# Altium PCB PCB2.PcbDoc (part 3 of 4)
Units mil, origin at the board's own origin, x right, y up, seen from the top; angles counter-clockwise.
Board outline 7170.03 x 5785.03 mil, 4 copper layers (Top Layer, GND, PWR, Bottom Layer), stack 22.378 mil thick; 348 components, 320 nets, 1937 pads, 429 vias.
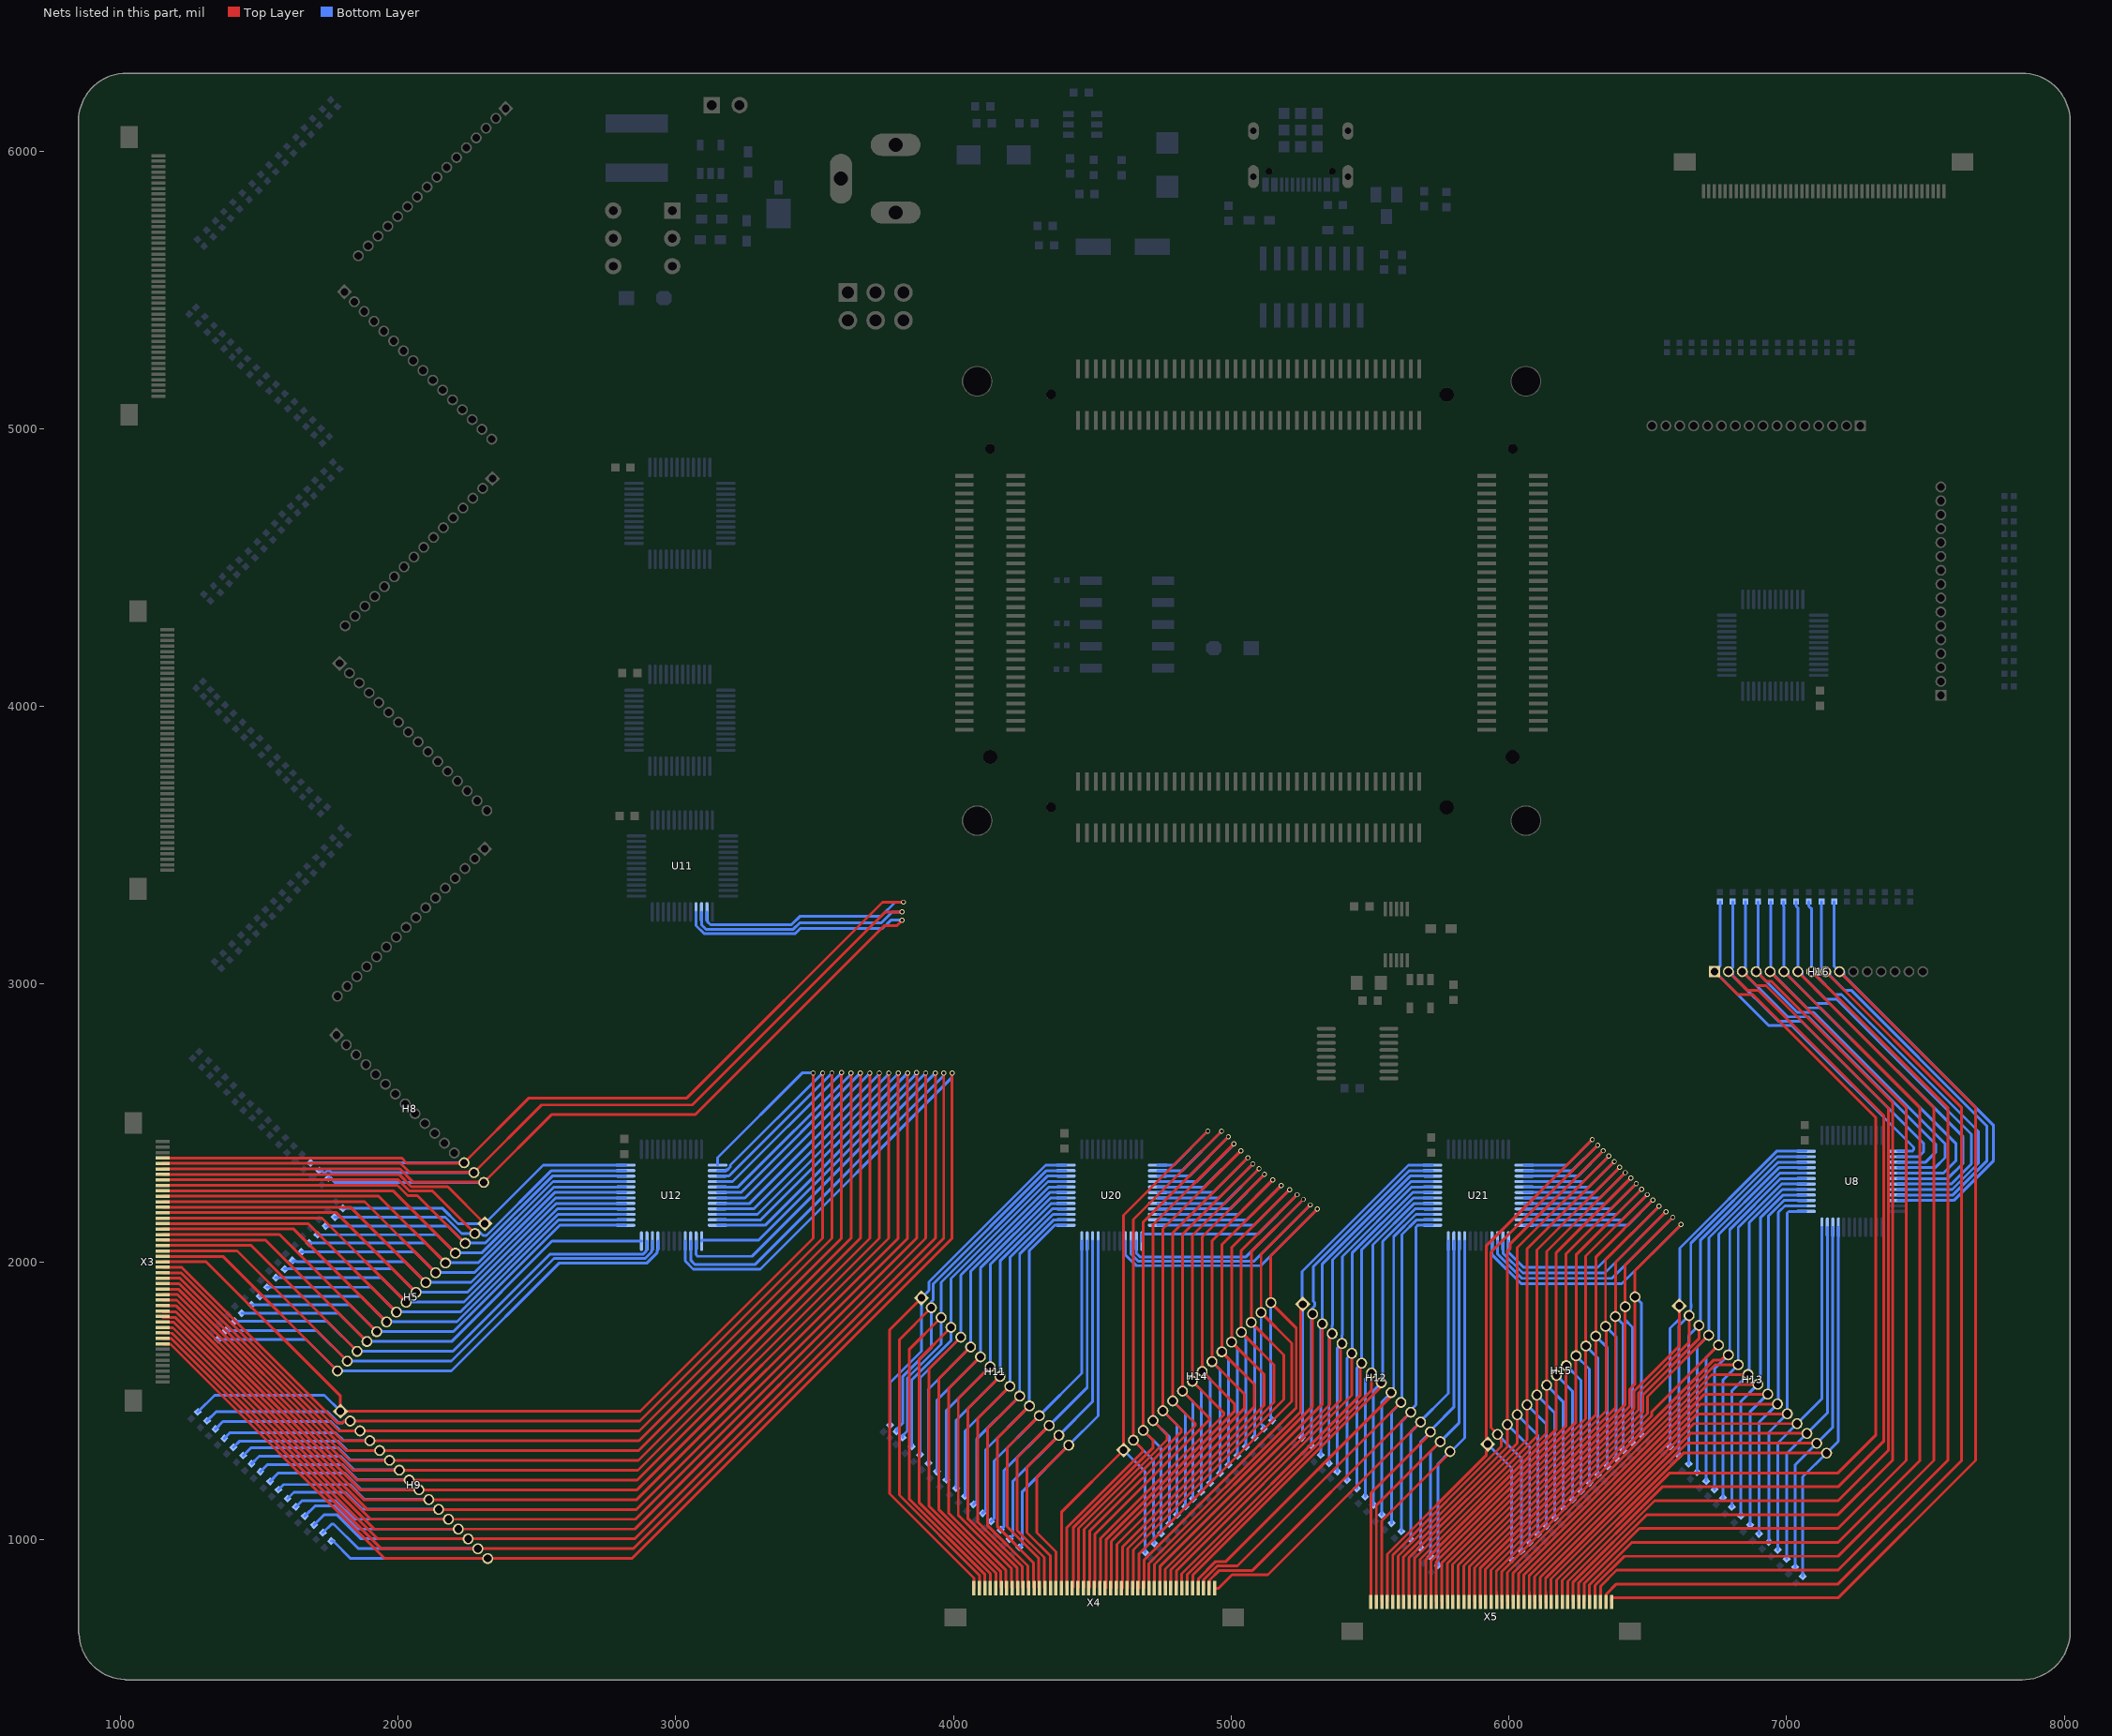
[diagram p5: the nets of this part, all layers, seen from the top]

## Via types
v1: diameter 18, hole 12, Top Layer to Bottom Layer, 429 vias

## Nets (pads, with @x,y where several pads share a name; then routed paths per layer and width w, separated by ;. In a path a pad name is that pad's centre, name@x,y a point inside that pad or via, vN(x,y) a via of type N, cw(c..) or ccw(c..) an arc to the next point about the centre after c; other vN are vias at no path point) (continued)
G93: H8.14 R201.2 U11.38 X3.4 | length 4400
  Top Layer w10: X3.4@1152.76,2374.02 2013,2374.02 2032.02,2355 2238.2,2355 H8.14@2240,2356.8 ; H8.14@2238.2,2356.8 2471.4,2590 3040,2590 3745,3295 v1(3820,3295)
  Bottom Layer w10: R201.2@1684.69,2356.89 1691.76,2356.89 1691.85,2356.8 H8.14@2238.2,2356.8 ; U11.38@3112.48,3260 3112.48,3229.8 3115.66,3226.62 3115.66,3223.24 3125.33,3213.57 3416.95,3213.57 3448.38,3245 3740,3245 3790,3295 v1(3820,3295)
G94: H8.15 R203.2 U11.39 X3.5 | length 4431.3
  Top Layer w10: X3.5@1152.76,2354.33 2010.06,2354.33 2042.28,2322.12 2272.88,2322.12 H8.15@2273.55,2321.45 2517.11,2565 3060,2565 3755,3260 v1(3815,3260)
  Bottom Layer w10: R203.2@1716.74,2328.94 1723.81,2328.94 1731.3,2321.45 1738.66,2321.45 1745.49,2328.28 1754.61,2328.28 1761.44,2321.45 H8.15@2273.55,2321.45 ; U11.39@3092.8,3260 3092.8,3213.68 3108.92,3197.57 3423.58,3197.57 3446.01,3220 3740,3220 3780,3260 v1(3815,3260)
G95: H8.16 R205.2 U11.40 X3.6 | length 4462.4
  Top Layer w10: X3.6@1152.76,2334.65 2007.12,2334.65 2055.01,2286.76 2308.24,2286.76 H8.16@2308.91,2286.09 2552.82,2530 3070,2530 3750,3210 3795,3210 v1(3815,3230)
  Bottom Layer w10: R205.2@1749.69,2301.89 1756.76,2301.89 1772.56,2286.09 H8.16@2308.91,2286.09 ; U11.40@3073.11,3260 3073.11,3210.74 3102.29,3181.57 3430.2,3181.57 3448.64,3200 3744.59,3200 3774.59,3230 v1(3815,3230)
G96: H5.1 R207.2 U12.12 X3.7 | length 2361.7
  Top Layer w10: X3.7@1152.76,2314.96 2004.18,2314.96 2048.38,2270.76 2179.21,2270.76 H5.1@2312.49,2137.49
  Bottom Layer w10: R207.2@1801.21,2192.36 2161.45,2192.36 2216.32,2137.49 H5.1@2312.49,2137.49 2523.27,2348.27 U12.12@2819.64,2348.27
G97: H5.2 R209.2 U12.11 X3.8 | length 2385
  Top Layer w10: X3.8@1152.76,2295.28 2001.23,2295.28 2041.75,2254.76 2124.5,2254.76 H5.2@2277.13,2102.13
  Bottom Layer w10: R209.2@1772.21,2160.6 2170.58,2160.6 2229.05,2102.13 H5.2@2277.13,2102.13 2287.96,2112.96 2306.27,2094.65 2318.7,2094.65 2552.63,2328.58 U12.11@2819.64,2328.58
G98: H5.3 R211.2 U12.10 X3.9 | length 2390.2
  Top Layer w10: X3.9@1152.76,2275.59 1998.3,2275.59 2035.12,2238.76 2069.79,2238.76 H5.3@2241.78,2066.78
  Bottom Layer w10: R211.2@1739.26,2128.55 2180.01,2128.55 H5.3@2241.78,2066.78 2252.61,2077.61 2262.77,2067.45 2314.13,2067.45 2555.58,2308.9 U12.10@2819.64,2308.9
G99: H5.4 R213.2 U12.9 X3.10 | length 2398.8
  Top Layer w10: X3.10@1152.76,2255.91 1981.93,2255.91 H5.4@2206.42,2031.42
  Bottom Layer w10: R213.2@1710.16,2097.64 2140.2,2097.64 H5.4@2206.42,2031.42 2217.25,2042.25 2227.41,2032.09 2301.4,2032.09 2558.52,2289.21 U12.9@2819.64,2289.21
G100: H5.5 R215.2 U12.8 X3.11 | length 2408.6
  Top Layer w10: X3.11@1152.76,2236.22 1930.91,2236.22 H5.5@2171.07,1996.07
  Bottom Layer w10: R215.2@1680.16,2067.64 2099.49,2067.64 H5.5@2171.07,1996.07 2181.9,2006.9 2192.05,1996.74 2288.67,1996.74 2561.46,2269.53 U12.8@2819.64,2269.53
G101: H5.6 R217.2 U12.7 X3.12 | length 2415.6
  Top Layer w10: X3.12@1152.76,2216.54 1879.88,2216.54 H5.6@2135.71,1960.71
  Bottom Layer w10: R217.2@1652.21,2035.6 1652.57,2035.24 2061.18,2035.24 H5.6@2135.71,1960.71 2146.54,1971.54 2156.7,1961.38 2275.94,1961.38 2564.4,2249.84 U12.7@2819.64,2249.84
G102: H5.7 R219.2 U12.6 X3.13 | length 2429.3
  Top Layer w10: X3.13@1152.76,2196.85 1828.86,2196.85 H5.7@2100.36,1925.36
  Bottom Layer w10: R219.2@1619.82,2000 1624.46,2004.64 1628.32,2004.64 1632.96,2000 2025.71,2000 H5.7@2100.36,1925.36 2111.18,1936.18 2121.34,1926.03 2263.21,1926.03 2567.35,2230.16 U12.6@2819.64,2230.16
G103: H5.8 R221.2 U12.5 X3.14 | length 2435.2
  Top Layer w10: X3.14@1152.76,2177.17 1777.83,2177.17 H5.8@2065,1890
  Bottom Layer w10: R221.2@1592.21,1975.6 1979.4,1975.6 H5.8@2065,1890 2075.83,1900.83 2085.99,1890.67 2250.49,1890.67 2570.29,2210.47 U12.5@2819.64,2210.47
G104: H5.9 R223.2 U12.4 X3.15 | length 2445.9
  Top Layer w10: X3.15@1152.76,2157.48 1726.81,2157.48 H5.9@2029.64,1854.64
  Bottom Layer w10: R223.2@1560.16,1942.64 1941.64,1942.64 H5.9@2029.64,1854.64 2040.47,1865.47 2050.63,1855.32 2237.76,1855.32 2573.23,2190.79 U12.4@2819.64,2190.79
G105: H5.10 R225.2 U12.3 X3.16 | length 2455
  Top Layer w10: X3.16@1152.76,2137.8 1675.78,2137.8 H5.10@1994.29,1819.29
  Bottom Layer w10: R225.2@1529.26,1908.55 1905.03,1908.55 H5.10@1994.29,1819.29 2005.12,1830.12 2015.28,1819.96 2225.03,1819.96 2576.17,2171.1 U12.3@2819.64,2171.1
G106: H5.11 R227.2 U12.2 X3.17 | length 2460.6
  Top Layer w10: X3.17@1152.76,2118.11 1624.76,2118.11 H5.11@1958.93,1783.93
  Bottom Layer w10: R227.2@1502.21,1875.6 1867.27,1875.6 H5.11@1958.93,1783.93 1969.76,1794.76 1979.92,1784.6 2212.3,1784.6 2579.12,2151.42 U12.2@2819.64,2151.42
G107: H5.12 R229.2 U12.1 X3.18 | length 2470.5
  Top Layer w10: X3.18@1152.76,2098.43 1573.73,2098.43 H5.12@1923.58,1748.58
  Bottom Layer w10: R229.2@1472.21,1845.6 1826.56,1845.6 H5.12@1923.58,1748.58 1934.41,1759.41 1944.57,1749.25 2199.57,1749.25 2582.06,2131.73 U12.1@2819.64,2131.73
G108: H5.13 R231.2 U12.48 X3.19 | length 2518.5
  Top Layer w10: X3.19@1152.76,2078.74 1522.71,2078.74 H5.13@1888.22,1713.22
  Bottom Layer w10: R231.2@1437.21,1815.6 1785.85,1815.6 H5.13@1888.22,1713.22 2193.22,1713.22 2554.64,2074.64 U12.48@2876.73,2074.64
G109: H5.14 R233.2 U12.47 X3.20 | length 2570.9
  Top Layer w10: X3.20@1152.76,2059.06 1471.67,2059.06 H5.14@1852.87,1677.87
  Bottom Layer w10: R233.2@1412.21,1785.6 1745.14,1785.6 H5.14@1852.87,1677.87 2197.87,1677.87 2548.21,2028.21 2883.57,2028.21 2893.24,2037.88 2893.24,2041.27 2896.42,2044.45 U12.47@2896.42,2074.64
G110: H5.15 R235.2 U12.46 X3.21 | length 2611.1
  Top Layer w10: X3.21@1152.76,2039.37 1420.66,2039.37 H5.15@1817.51,1642.51
  Bottom Layer w10: R235.2@1380.16,1752.64 1707.38,1752.64 H5.15@1817.51,1642.51 2192.51,1642.51 2562.21,2012.21 2890.2,2012.21 2912.93,2034.95 2912.93,2040.83 2912.93,2041.28 2916.1,2044.45 U12.46@2916.1,2074.64
G111: H5.16 R237.2 U12.45 X3.22 | length 2647.6
  Top Layer w10: X3.22@1152.76,2019.69 1369.62,2019.69 H5.16@1782.16,1607.16
  Bottom Layer w10: R237.2@1352.21,1720.6 1668.72,1720.6 H5.16@1782.16,1607.16 2192.16,1607.16 2581.21,1996.21 2896.82,1996.21 2932.61,2032 2932.61,2040.82 2932.61,2041.27 2935.79,2044.45 U12.45@2935.79,2074.64
G112: H9.1 R239.2 U12.25 X3.23 | length 4510.3
  Top Layer w10: X3.23@1152.76,2000 1310,2000 1792.87,1517.13 H9.1@1792.87,1462.13 2872.13,1462.13 3495,2085 v1(3495,2680)
  Bottom Layer w10: R239.2@1279.66,1459.69 1339.97,1520 1735,1520 H9.1@1792.87,1462.13 ; U12.25@3150.36,2348.27 3150.36,2375.36 3455,2680 v1(3495,2680)
G113: H9.2 R241.2 U12.26 X3.24 | length 4556.3
  Top Layer w10: X3.24@1152.76,1980.32 1221.31,1980.32 1782.34,1419.29 1799.08,1419.29 1806.56,1426.78 H9.2@1828.22,1426.78 2870.78,1426.78 3529,2085 v1(3529,2680)
  Bottom Layer w10: R241.2@1312.61,1427.64 1344.97,1460 1745.95,1460 1786.65,1419.29 1799.08,1419.29 1806.56,1426.78 H9.2@1828.22,1426.78 ; U12.26@3150.36,2328.58 3180.55,2328.58 3183.73,2331.76 3187.12,2331.76 3196.79,2341.43 3196.79,2347.79 v1(3529,2680)
G114: H9.3 R243.2 U12.27 X3.25 | length 4641.1
  Top Layer w10: X3.25@1152.76,1960.63 1218.37,1960.63 1787.58,1391.42 H9.3@1863.58,1391.42 2868.96,1391.42 3562.54,2085 v1(3562.54,2680.46)
  Bottom Layer w10: R243.2@1342.61,1397.64 1369.97,1425 1758.32,1425 1791.23,1392.09 1862.91,1392.09 H9.3@1863.58,1391.42 ; U12.27@3150.36,2308.9 3150.55,2309.1 3192.04,2309.1 3562.54,2679.6 v1(3562.54,2680.46)
G115: H9.4 R245.2 U12.28 X3.26 | length 4738
  Top Layer w10: X3.26@1152.76,1940.95 1215.43,1940.95 1800.31,1356.07 H9.4@1898.93,1356.07 2868.07,1356.07 3597,2085 v1(3597,2680.99)
  Bottom Layer w10: R245.2@1374.66,1364.69 1394.97,1385 1775.69,1385 1803.96,1356.74 1898.26,1356.74 H9.4@1898.93,1356.07 ; U12.28@3150.36,2289.21 3205.22,2289.21 v1(3597,2680.99)
G116: H9.5 R247.2 U12.29 X3.27 | length 4843.4
  Top Layer w10: X3.27@1152.76,1921.26 1212.49,1921.26 1813.04,1320.71 H9.5@1934.29,1320.71 2866.71,1320.71 3631,2085 v1(3631,2680)
  Bottom Layer w10: R247.2@1407.61,1332.64 1429.97,1355 1783.07,1355 1816.68,1321.38 1933.62,1321.38 H9.5@1934.29,1320.71 ; U12.29@3150.36,2269.53 3224.53,2269.53 v1@3635,2680
G117: H9.6 R249.2 U12.30 X3.28 | length 4943.4
  Top Layer w10: X3.28@1152.76,1901.58 1209.54,1901.58 1825.77,1285.36 H9.6@1969.64,1285.36 2865.36,1285.36 3665,2085 v1(3665,2680)
  Bottom Layer w10: R249.2@1442.61,1302.64 1469.97,1330 1785.44,1330 1829.41,1286.03 1968.97,1286.03 H9.6@1969.64,1285.36 ; U12.30@3150.36,2249.84 3234.84,2249.84 v1(3665,2680)
G118: H9.7 R251.2 U12.31 X3.29 | length 5048.3
  Top Layer w10: X3.29@1152.76,1881.89 1206.6,1881.89 1838.5,1250 H9.7@2005,1250 2864,1250 3699,2085 v1(3699,2680)
  Bottom Layer w10: R251.2@1472.61,1272.64 1499.97,1300 1792.81,1300 1842.14,1250.67 2004.33,1250.67 H9.7@2005,1250 ; U12.31@3150.36,2230.16 3249.16,2230.16 v1(3699,2680)
G119: H9.8 R253.2 U12.32 X3.30 | length 5151.1
  Top Layer w10: X3.30@1152.76,1862.21 1203.66,1862.21 1851.22,1214.64 H9.8@2040.36,1214.64 2862.64,1214.64 3733,2085 v1(3733,2680)
  Bottom Layer w10: R253.2@1504.66,1244.69 1529.97,1270 1800.18,1270 1854.87,1215.32 2039.68,1215.32 H9.8@2040.36,1214.64 ; U12.32@3150.36,2210.47 3266.53,2210.47 v1@3734.53,2678.47
G120: H9.9 R255.2 U12.33 X3.31 | length 5254.6
  Top Layer w10: X3.31@1152.76,1842.52 1200.72,1842.52 1863.95,1179.29 H9.9@2075.71,1179.29 2861.29,1179.29 3767,2085 v1(3767,2680)
  Bottom Layer w10: R255.2@1540.02,1210.05 1569.97,1240 1807.56,1240 1867.6,1179.96 2075.04,1179.96 H9.9@2075.71,1179.29 ; U12.33@3150.36,2190.79 3280.79,2190.79 v1@3770,2680
G121: H9.10 R257.2 U12.34 X3.32 | length 5350.8
  Top Layer w10: X3.32@1152.76,1822.84 1152.76,1820.06 1200.56,1820.06 1876.68,1143.93 H9.10@2111.07,1143.93 2859.93,1143.93 3801,2085 v1(3801,2680)
  Bottom Layer w10: R257.2@1569.66,1179.69 1588.14,1198.17 1826.75,1198.17 1880.32,1144.6 2110.4,1144.6 H9.10@2111.07,1143.93 ; U12.34@3150.36,2171.1 3294.32,2171.1 3797,2673.78 3797,2673.84 3802.97,2679.81 v1@3803.03,2679.81
G122: H9.11 R259.2 U12.35 X3.33 | length 5452.6
  Top Layer w10: X3.33@1152.76,1803.15 1152.76,1800.38 1197.61,1800.38 1889.41,1108.58 H9.11@2146.42,1108.58 2858.58,1108.58 3835,2085 v1(3835,2680)
  Bottom Layer w10: R259.2@1602.97,1148 1624.97,1170 1809.67,1170 1870.42,1109.25 2145.75,1109.25 H9.11@2146.42,1108.58 ; U12.35@3150.36,2151.42 3306.42,2151.42 v1(3835,2680)
G123: H9.12 R261.2 U12.36 X3.34 | length 5557.3
  Top Layer w10: X3.34@1152.76,1783.47 1153.66,1782.57 1192.79,1782.57 1902.14,1073.22 H9.12@2181.78,1073.22 2855.75,1073.22 3867.53,2085 v1(3867.53,2681.47)
  Bottom Layer w10: R261.2@1632.61,1117.64 1654.34,1139.37 1775.63,1139.37 1841.78,1073.22 H9.12@2181.78,1073.22 ; U12.36@3150.36,2131.73 3321.73,2131.73 3859,2669 3859,2670.78 3867.53,2679.31 v1(3867.53,2681.47)
G124: H9.13 R263.2 U12.37 X3.35 | length 5737.4
  Top Layer w10: X3.35@1152.76,1763.78 1153.66,1762.88 1189.86,1762.88 1914.86,1037.87 H9.13@2217.13,1037.87 2852.87,1037.87 3900,2085 v1(3900,2680)
  Bottom Layer w10: R263.2@1664.66,1084.69 1700.84,1120.87 1771.5,1120.87 1854.5,1037.87 H9.13@2217.13,1037.87 ; U12.37@3093.27,2074.64 3093.27,2077.03 3093.74,2077.5 3297.5,2077.5 v1(3900,2680)
G125: H9.14 R265.2 U12.38 X3.36 | length 5925.4
  Top Layer w10: X3.36@1152.76,1744.1 1153.66,1743.2 1186.91,1743.2 1927.59,1002.51 H9.14@2252.49,1002.51 2852.51,1002.51 3935,2085 v1(3935,2680)
  Bottom Layer w10: R265.2@1697.61,1052.64 1734.97,1090 1779.75,1090 1867.23,1002.51 H9.14@2252.49,1002.51 ; U12.38@3073.58,2074.64 3073.58,2025.86 3079.44,2020 3275,2020 v1(3935,2680)
G126: H9.15 R267.2 U12.39 X3.37 | length 6069.3
  Top Layer w10: X3.37@1152.76,1724.41 1153.66,1723.51 1183.97,1723.51 1940.32,967.16 H9.15@2287.84,967.16 2847.16,967.16 3965,2085 v1(3965,2680)
  Bottom Layer w10: R267.2@1730.02,1025.05 1760.84,1055.87 1769.13,1055.87 1857.84,967.16 H9.15@2287.84,967.16 ; U12.39@3053.9,2074.64 3053.9,2006.1 3070,1990 3285,1990 3963.47,2668.47 3963.47,2678.47 v1(3965,2680)
G127: H9.16 R269.2 U12.40 X3.38 | length 6170.2
  Top Layer w10: X3.38@1152.76,1704.73 1153.66,1703.83 1181.02,1703.83 1953.05,931.8 H9.16@2323.2,931.8 2841.8,931.8 3995,2085 v1(3995,2680)
  Bottom Layer w10: R269.2@1759.66,994.69 1766.73,994.69 1829.62,931.8 H9.16@2323.2,931.8 ; U12.40@3034.21,2074.64 3034.21,2003.16 3063.37,1974 3304,1974 3995,2665 v1(3995,2680)
G128: H11.1 R13.2 U20.12 X4.1 | length 2459.6
  Top Layer w10: H11.1@3884.84,1870.16 3769.84,1755.16 3769.84,1165.17 4073.82,861.18 X4.1@4073.82,825
  Bottom Layer w10: R13.2@3772.05,1412.05 3772.05,1565.05 3884.84,1677.83 H11.1@3884.84,1870.16 3911.67,1897 3911.67,1928.09 4331.85,2348.27 U20.12@4404.64,2348.27
G129: H11.2 R15.2 U20.11 X4.2 | length 2408.9
  Top Layer w10: H11.2@3920.19,1834.81 3805.19,1719.81 3805.19,1159.81 4093.5,871.5 X4.2@4093.5,824.94
  Bottom Layer w10: R15.2@3795,1390 3795,1397.07 3818,1420.07 3818,1588.37 3920.19,1690.56 H11.2@3920.19,1834.81 3920.19,1856.47 3927.67,1863.95 3927.67,1921.47 4334.79,2328.58 U20.11@4404.64,2328.58
G130: H11.3 R17.2 U20.10 X4.3 | length 2359.5
  Top Layer w10: H11.3@3955.55,1799.45 3840.55,1684.45 3840.55,1147.08 4113.19,874.44 X4.3@4113.19,825
  Bottom Layer w10: R17.2@3817.05,1367.05 3817.05,1374.12 3834,1391.07 3834,1581.74 3955.55,1703.29 H11.3@3955.55,1799.45 3955.55,1926.71 4337.73,2308.9 U20.10@4404.64,2308.9
G131: H11.4 R19.2 U20.9 X4.4 | length 2314.6
  Top Layer w10: H11.4@3990.9,1764.1 3875.9,1649.1 3875.9,1134.35 4132.87,877.38 X4.4@4132.87,825
  Bottom Layer w10: R19.2@3850,1335 3850,1575.11 3990.9,1716.02 H11.4@3990.9,1764.1 3990.9,1939.44 4340.67,2289.21 U20.9@4404.64,2289.21
G132: H11.5 R21.2 U20.8 X4.5 | length 2268.9
  Top Layer w10: H11.5@4026.26,1728.74 3911.26,1613.74 3911.26,1121.63 4152.56,880.32 X4.5@4152.56,825
  Bottom Layer w10: R21.2@3880,1305 3880,1582.49 H11.5@4026.26,1728.74 4026.26,1952.17 4343.62,2269.53 U20.8@4404.64,2269.53
G133: H11.6 R23.2 U20.7 X4.6 | length 2223.2
  Top Layer w10: H11.6@4061.61,1693.39 3946.61,1578.39 3946.61,1108.9 4169.47,886.04 4169.47,827.77 X4.6@4172.24,825
  Bottom Layer w10: R23.2@3910,1275 3910,1541.78 H11.6@4061.61,1693.39 4061.61,1964.9 4346.56,2249.84 U20.7@4404.64,2249.84
G134: H11.7 R25.2 U20.6 X4.7 | length 2177.6
  Top Layer w10: H11.7@4096.97,1658.03 3981.97,1543.03 3981.97,1096.17 4189.15,888.99 4189.15,827.78 X4.7@4191.93,825
  Bottom Layer w10: R25.2@3940,1245 3940,1501.07 H11.7@4096.97,1658.03 4096.97,1977.62 4349.5,2230.16 U20.6@4404.64,2230.16
G135: H11.8 R27.2 U20.5 X4.8 | length 2129.8
  Top Layer w10: H11.8@4132.32,1622.68 4017.32,1507.68 4017.32,1087.68 4208.84,896.16 4208.84,827.77 X4.8@4211.61,825
  Bottom Layer w10: R27.2@3975,1215 3975,1465.36 H11.8@4132.32,1622.68 4132.32,1990.35 4352.44,2210.47 U20.5@4404.64,2210.47
G136: H11.9 R29.2 U20.4 X4.9 | length 2082.1
  Top Layer w10: H11.9@4167.68,1587.32 4052.68,1472.32 4052.68,1074.95 4228.52,899.11 4228.52,827.78 X4.9@4231.3,825
  Bottom Layer w10: R29.2@4010,1185 4010,1429.64 H11.9@4167.68,1587.32 4167.68,2003.08 4355.39,2190.79 U20.4@4404.64,2190.79
G137: H11.10 R31.2 U20.3 X4.10 | length 2033.5
  Top Layer w10: H11.10@4203.03,1551.97 4088.03,1436.97 4088.03,1062.22 4248.21,902.05 4248.21,827.77 X4.10@4250.98,825
  Bottom Layer w10: R31.2@4042.05,1157.05 4042.05,1390.98 H11.10@4203.03,1551.97 4203.03,2015.81 4358.33,2171.1 U20.3@4404.64,2171.1
G138: H11.11 R33.2 U20.2 X4.11 | length 1987.8
  Top Layer w10: H11.11@4238.39,1516.61 4123.39,1401.61 4123.39,1049.49 4267.89,905 4267.89,827.78 X4.11@4270.67,825
  Bottom Layer w10: R33.2@4072.05,1127.05 4083.46,1138.46 4083.46,1361.68 H11.11@4238.39,1516.61 4238.39,2028.53 4361.27,2151.42 U20.2@4404.64,2151.42
G139: H11.12 R35.2 U20.1 X4.12 | length 1942.9
  Top Layer w10: H11.12@4273.74,1481.26 4158.74,1366.26 4158.74,1046.26 4287.58,917.42 4287.58,827.77 X4.12@4290.35,825
  Bottom Layer w10: R35.2@4105,1095 4116.41,1106.41 4116.41,1323.92 H11.12@4273.74,1481.26 4273.74,2041.26 4364.21,2131.73 U20.1@4404.64,2131.73
G140: H11.13 R37.2 U20.48 X4.13 | length 1861.5
  Top Layer w10: H11.13@4309.1,1445.9 4194.1,1330.9 4194.1,1045.9 4307.26,932.74 4307.26,827.78 X4.13@4310.04,825
  Bottom Layer w10: R37.2@4135,1065 4146.41,1076.41 4146.41,1283.21 H11.13@4309.1,1445.9 4461.73,1598.53 U20.48@4461.73,2074.64
G141: H11.14 R39.2 U20.47 X4.14 | length 1843.3
  Top Layer w10: X4.14@4329.72,825 4326.95,827.77 4326.95,935.68 4229.45,1033.17 4229.45,1295.55 H11.14@4344.45,1410.55
  Bottom Layer w10: R39.2@4170,1035 4181.41,1046.41 4181.41,1247.5 H11.14@4344.45,1410.55 4481.42,1547.51 U20.47@4481.42,2074.64
G142: H11.15 R41.2 U20.46 X4.15 | length 1829.3
  Top Layer w10: X4.15@4349.41,825 4349.41,940.59 4264.81,1025.19 4264.81,1260.19 H11.15@4379.81,1375.19
  Bottom Layer w10: R41.2@4202.05,1002.05 4213.46,1013.46 4213.46,1208.84 H11.15@4379.81,1375.19 4501.1,1496.48 U20.46@4501.1,2074.64
G143: H11.16 R43.2 U20.45 X4.16 | length 1811.1
  Top Layer w10: X4.16@4369.09,825 4369.09,955.91 4300.16,1024.84 4300.16,1224.84 H11.16@4415.16,1339.84
  Bottom Layer w10: R43.2@4237.05,972.05 4248.46,983.46 4248.46,1173.13 H11.16@4415.16,1339.84 4520.79,1445.46 U20.45@4520.79,2074.64
G144: H14.1 R45.2 U20.25 X4.17 | length 2496.4
  Top Layer w10: X4.17@4388.78,825 4388.78,1098.78 H14.1@4612.51,1322.51 4612.51,2167.51 v1(4916,2471)
  Bottom Layer w10: H14.1@4612.51,1322.51 4689.91,1245.12 R45.2@4689.91,954.01 ; U20.25@4735.36,2348.27 4793.27,2348.27 v1(4916,2471)
G145: H14.2 R47.2 U20.26 X4.18 | length 2593
  Top Layer w10: X4.18@4408.46,825 4408.46,1043.46 4681.23,1316.23 4681.23,1324.51 H14.2@4647.87,1357.87 4647.87,2152.87 v1(4965,2470)
  Bottom Layer w10: H14.2@4647.87,1357.87 4720.57,1285.17 4720.57,1017.76 4721.96,1016.37 R47.2@4721.96,986.96 ; U20.26@4735.36,2328.58 4823.58,2328.58 v1(4965,2470)
G146: H14.3 R49.2 U20.27 X4.19 | length 2598.2
  Top Layer w10: X4.19@4428.15,825 4430.92,827.77 4430.92,1043.3 4719.08,1331.45 4719.08,1357.37 H14.3@4683.22,1393.22 4683.22,2143.22 v1(4990,2450)
  Bottom Layer w10: H14.3@4683.22,1393.22 4746.96,1329.49 R49.2@4746.96,1021.96 ; U20.27@4735.36,2308.9 4848.9,2308.9 v1(4990,2450)
G147: H14.4 R51.2 U20.28 X4.20 | length 2603
  Top Layer w10: X4.20@4447.83,825 4450.61,827.78 4450.61,1040.36 4769.44,1359.18 4769.44,1377.72 H14.4@4718.58,1428.58 4718.58,2133.58 v1(5010,2425)
  Bottom Layer w10: H14.4@4718.58,1428.58 4776.96,1370.2 R51.2@4776.96,1056.96 ; U20.28@4735.36,2289.21 4876.37,2289.21 5010,2422.84 v1(5010,2425)
G148: H14.5 R53.2 U20.29 X4.21 | length 2614.3
  Top Layer w10: X4.21@4467.52,825 4470.29,827.77 4470.29,1037.41 4819.79,1386.91 4819.79,1398.08 H14.5@4753.93,1463.93 4753.93,2118.93 v1(5035,2400)
  Bottom Layer w10: U20.29@4735.36,2269.53 4903.47,2269.53 5033.94,2400 v1(5035,2400) ; H14.5@4753.93,1463.93 4804.91,1412.96 R53.2@4804.91,1089.01
G149: H14.6 R55.2 U20.30 X4.22 | length 2629.9
  Top Layer w10: X4.22@4487.2,825 4489.98,827.78 4489.98,1029.98 4870.15,1410.15 4870.15,1418.43 H14.6@4789.29,1499.29 4789.29,2104.29 v1(5060,2375)
  Bottom Layer w10: U20.30@4735.36,2249.84 4934.84,2249.84 v1(5060,2375) ; H14.6@4789.29,1499.29 4834.91,1453.67 R55.2@4834.91,1119.01
G150: H14.7 R57.2 U20.31 X4.23 | length 2639.2
  Top Layer w10: X4.23@4506.89,825 4509.66,827.77 4509.66,1019.66 4920.5,1430.5 4920.5,1438.79 H14.7@4824.64,1534.64 4824.64,2098.93 v1(5077.86,2352.14)
  Bottom Layer w10: U20.31@4735.36,2230.16 4955.88,2230.16 v1(5077.86,2352.14) ; H14.7@4824.64,1534.64 4861.96,1497.33 R57.2@4861.96,1146.96
G151: H14.8 R59.2 U20.32 X4.24 | length 2670.3
  Top Layer w10: X4.24@4526.57,825 4526.57,845.59 4528.98,845.59 4529.35,845.96 4529.35,1004.35 4973.36,1448.36 4973.36,1456.64 H14.8@4860,1570 4860,2095 v1(5100,2335)
  Bottom Layer w10: U20.32@4735.36,2210.47 4975.47,2210.47 v1(5100,2335) ; H14.8@4860,1570 4891.96,1538.04 R59.2@4891.96,1171.96
G152: H14.9 R61.2 U20.33 X4.25 | length 2676.3
  Top Layer w10: X4.25@4546.26,825 4549.03,825 4549.03,999.03 5012.86,1462.86 5012.86,1487.86 H14.9@4895.36,1605.36 4895.36,2090.36 v1(5120,2315)
  Bottom Layer w10: U20.33@4735.36,2190.79 4995.79,2190.79 v1(5120,2315) ; H14.9@4895.36,1605.36 4924.91,1575.8 R61.2@4924.91,1204.01
G153: H14.10 R63.2 U20.34 X4.26 | length 2690.7
  Top Layer w10: X4.26@4565.94,825 4568.72,825 4568.72,993.72 5048.21,1473.21 5048.21,1523.21 H14.10@4930.71,1640.71 4930.71,2075.71 v1(5150,2295)
  Bottom Layer w10: U20.34@4735.36,2171.1 5026.1,2171.1 v1(5150,2295) ; H14.10@4930.71,1640.71 4959.91,1611.51 R63.2@4959.91,1239.01
G154: H14.11 R65.2 U20.35 X4.27 | length 2707.9
  Top Layer w10: X4.27@4585.63,825 4588.4,825 4588.4,983.4 5083.57,1478.57 5083.57,1558.57 H14.11@4966.07,1676.07 4966.07,2061.07 v1(5180,2275)
  Bottom Layer w10: U20.35@4735.36,2151.42 5056.42,2151.42 v1(5180,2275) ; H14.11@4966.07,1676.07 4989.91,1652.22 R65.2@4989.91,1269.01
G155: H14.12 R67.2 U20.36 X4.28 | length 2730.2
  Top Layer w10: X4.28@4605.31,825 4608.09,825 4608.09,973.09 5118.92,1483.92 5118.92,1593.92 H14.12@5001.42,1711.42 5001.42,2051.42 v1(5210,2260)
  Bottom Layer w10: U20.36@4735.36,2131.73 5081.73,2131.73 v1(5210,2260) ; H14.12@5001.42,1711.42 5021.96,1690.88 R67.2@5021.96,1301.96
G156: H14.13 R69.2 U20.37 X4.29 | length 2833
  Top Layer w10: X4.29@4625,825 4627.77,825 4627.77,967.77 5154.28,1494.28 5154.28,1629.28 H14.13@5036.78,1746.78 5035,1748.55 5035,2039.2 v1(5237.6,2241.8)
  Bottom Layer w10: U20.37@4678.27,2074.64 4678.27,2099.09 4678.74,2099.57 5095.36,2099.57 v1(5237.6,2241.8) ; H14.13@5036.78,1746.78 5052.55,1731 R69.2@5052.55,1334.17
G157: H14.14 R71.2 U20.38 X4.30 | length 2909.9
  Top Layer w10: X4.30@4644.68,825 4647.46,825 4647.46,962.46 5189.63,1504.63 5189.63,1664.63 H14.14@5072.13,1782.13 5072.13,2037.13 v1(5260,2225)
  Bottom Layer w10: U20.38@4658.58,2074.64 4658.58,2031.27 4671.64,2018.21 5053.21,2018.21 v1(5260,2225) ; H14.14@5072.13,1782.13 5084.6,1769.66 R71.2@5084.6,1367.12
G158: H14.15 R73.2 U20.39 X4.31 | length 2940
  Top Layer w10: X4.31@4664.37,825 4667.14,825 4667.14,947.14 5218,1498 5218,1706.97 H14.15@5107.49,1817.49 5107.49,2027.49 v1(5285,2205)
  Bottom Layer w10: U20.39@4638.9,2074.64 4638.9,2028.33 4665.02,2002.21 5082.21,2002.21 v1(5285,2205) ; H14.15@5107.49,1817.49 5107.49,1416.31 5117.55,1406.24 R73.2@5117.55,1399.17
G159: H14.16 R75.2 U20.40 X4.32 | length 2967.7
  Top Layer w10: X4.32@4684.05,825 4686.83,825 4686.83,926.83 5234,1474 5234,1761.69 H14.16@5142.84,1852.84 5142.84,2022.84 v1(5310,2190)
  Bottom Layer w10: U20.40@4619.21,2074.64 4619.21,2025.39 4658.39,1986.21 5106.21,1986.21 v1(5310,2190) ; H14.16@5142.84,1852.84 5142.84,1440.95 5147.55,1436.24 R75.2@5147.55,1429.17
G160: H12.1 R77.2 U21.12 X4.33 | length 2476.8
  Top Layer w10: X4.33@4703.74,825 4703.74,913.74 5250,1460 5250,1834.92 5252.16,1837.07 5252.16,1848.31 H12.1@5250,1850.47
  Bottom Layer w10: R77.2@5254.28,1366.52 5254.28,1373.59 5257.51,1376.82 H12.1@5257.51,1847.49 ; H12.1@5255,1854.36 5255,1865.74 5257.51,1868.26 5255,1870.77 5255,1964.77 5638.5,2348.27 U21.12@5724.64,2348.27
G161: H12.2 R79.2 U21.11 X4.34 | length 2430.6
  Top Layer w10: X4.34@4723.42,825 4723.42,910.79 5292.87,1480.24 H12.2@5292.87,1812.13
  Bottom Layer w10: R79.2@5289.28,1336.52 5289.28,1808.54 H12.2@5292.87,1812.13 ; H12.2@5290.29,1831.21 5300.35,1841.27 5300.35,1853.7 5295,1859.06 5295,1982.14 5641.43,2328.58 U21.11@5724.64,2328.58
G162: H12.3 R81.2 U21.10 X4.35 | length 2412.3
  Top Layer w10: X4.35@4743.11,825 4743.11,903.11 5328.22,1488.22 H12.3@5328.22,1776.78
  Bottom Layer w10: R81.2@5322.23,1304.47 5322.23,1770.78 H12.3@5328.22,1776.78 5328.22,1992.74 5644.38,2308.9 U21.10@5724.64,2308.9
G163: H12.4 R83.2 U21.9 X4.36 | length 2377.7
  Top Layer w10: X4.36@4762.79,825 4762.79,893.68 5355,1485.89 H12.4@5355,1754.43
  Bottom Layer w10: R83.2@5352.23,1274.47 5352.23,1730.07 H12.4@5363.58,1741.42 ; H12.4@5365,1753.1 5363.84,1754.25 5363.84,1771.16 5365,1772.32 5365,2006.89 5647.32,2289.21 U21.9@5724.64,2289.21
G164: H12.5 R85.2 U21.8 X4.37 | length 2347.4
  Top Layer w10: X4.37@4782.48,825 4782.48,890.74 5393.58,1501.84 H12.5@5393.58,1716.42
  Bottom Layer w10: R85.2@5382.23,1244.47 5382.23,1689.36 H12.5@5398.93,1706.07 ; H12.5@5400,1713.86 5399.2,1714.66 5399.2,1736.16 5400,1736.96 5400,2019.26 5650.27,2269.53 U21.8@5724.64,2269.53
G165: H12.6 R87.2 U21.7 X4.38 | length 2294.3
  Top Layer w10: X4.38@4802.16,825 4802.16,887.16 5434.29,1519.29 H12.6@5434.29,1670.71
  Bottom Layer w10: R87.2@5417.23,1214.47 5417.23,1653.65 H12.6@5434.29,1670.71 ; H12.6@5435,1688.22 5435,2031.64 5653.2,2249.84 U21.7@5724.64,2249.84
G166: H12.7 R89.2 U21.6 X4.39 | length 2279.4
  Top Layer w10: X4.39@4821.85,825 4821.85,877.1 5465,1520.25 5465,1595.95 5464.96,1595.99 5464.96,1639.27 H12.7@5465,1639.31
  Bottom Layer w10: R89.2@5452.23,1184.47 5452.23,1617.94 H12.7@5469.64,1635.36 5469.64,2043.65 5656.15,2230.16 U21.6@5724.64,2230.16
G167: H12.8 R91.2 U21.5 X4.40 | length 2213.2
  Top Layer w10: X4.40@4841.53,825 4841.53,874.16 5505.67,1538.3 5505.67,1579.01
  Bottom Layer w10: R91.2@5482.23,1154.47 5482.23,1577.23 H12.8@5505,1600 ; H12.8@5510,1608.7 5510,2061.38 5659.09,2210.47 U21.5@5724.64,2210.47
G168: H12.9 R93.2 U21.4 X4.41 | length 2202.6
  Top Layer w10: X4.41@4861.22,825 4862.13,825.91 4862.13,872.13 5534.74,1544.74 5534.74,1551.08 5540.74,1557.09 H12.9@5547.09,1557.09
  Bottom Layer w10: R93.2@5512.23,1124.47 5512.23,1536.52 H12.9@5540.36,1564.64 ; H12.9@5545,1571.05 5545,2073.75 5662.04,2190.79 U21.4@5724.64,2190.79
G169: H12.10 R95.2 U21.3 X4.42 | length 2197.3
  Top Layer w10: X4.42@4880.9,825 4881.81,825.91 4881.81,859.15 4943.65,921 4981,921 5570.09,1510.09 5570.09,1515.72 H12.10@5580.35,1525.98
  Bottom Layer w10: R95.2@5542.23,1089.47 5542.23,1495.81 H12.10@5575.71,1529.29 ; H12.10@5581.33,1534.36 5581.33,1542.86 5585,1546.53 5585,2091.13 5664.97,2171.1 U21.3@5724.64,2171.1
G170: H12.11 R97.2 U21.2 X4.43 | length 2191.2
  Top Layer w10: X4.43@4900.59,825 4901.5,825.91 4901.5,856.22 4950.28,905 5022.13,905 H12.11@5611.07,1493.93 5612.78,1495.64 H12.11@5620.64,1495.64
  Bottom Layer w10: R97.2@5577.23,1059.47 5577.23,1460.1 H12.11@5611.07,1493.93 ; H12.11@5615,1502.98 5615,2098.5 5667.92,2151.42 U21.2@5724.64,2151.42
G171: H12.12 R99.2 U21.1 X4.44 | length 2185
  Top Layer w10: X4.44@4920.27,825 4921.18,825.91 4921.18,853.27 4956.91,889 5076.84,889 H12.12@5646.42,1458.58
  Bottom Layer w10: R99.2@5612.23,1029.47 5612.23,1424.38 H12.12@5646.42,1458.58 5646.42,1466.53 5665,1485.1 5665,2125.87 5670.86,2131.73 U21.1@5724.64,2131.73
G172: H12.13 R101.2 U21.48 X4.45 | length 2129.5
  Top Layer w10: X4.45@4939.96,825 4955.01,825.01 5003,873 5131.55,873 H12.13@5681.78,1423.22
  Bottom Layer w10: R101.2@5647.23,999.47 5647.23,1388.67 H12.13@5681.78,1423.22 ; H12.13@5672.92,1417.92 5781.73,1526.73 U21.48@5781.73,2074.64
G173: H12.14 R103.2 U21.47 X5.1 | length 1840
  Top Layer w10: X5.1@5502.92,775 5502.92,1167.68 H12.14@5725.28,1390.04
  Bottom Layer w10: R103.2@5682.23,969.47 5682.23,1352.96 H12.14@5717.13,1387.87 ; 5729.42,1404.42 5801.42,1476.42 U21.47@5801.42,2074.64
G174: H12.15 R105.2 U21.46 X5.2 | length 1865.9
  Top Layer w10: X5.2@5522.6,774.94 5522.6,1122.63 H12.15@5752.49,1352.51
  Bottom Layer w10: R105.2@5717.23,939.47 5717.23,1317.25 H12.15@5752.49,1352.51 ; H12.15@5741.93,1341.95 5821.1,1421.13 U21.46@5821.1,2074.64
G175: H12.16 R107.2 U21.45 X5.3 | length 1847.2
  Top Layer w10: X5.3@5542.29,775 5542.29,1067.29 H12.16@5790,1315
  Bottom Layer w10: R107.2@5744.28,906.52 5744.28,1273.59 H12.16@5787.84,1317.16 ; H12.16@5793.41,1318.41 5840.79,1365.79 U21.45@5840.79,2074.64
G176: H15.1 R109.2 U21.25 X5.4 | length 2706.8
  Top Layer w10: X5.4@5561.97,775 5561.97,947.54 5919,1304.57 5919,1318.23 5923.58,1322.81 5923.58,1339 5919,1343.58 5919,2059 v1(6300,2440)
  Bottom Layer w10: H15.1@5923.58,1343.58 6009.44,1257.72 R109.2@6009.44,929.48 ; U21.25@6055.36,2348.27 6208.27,2348.27 v1(6300,2440)
G177: H15.2 R111.2 U21.26 X5.5 | length 2739.4
  Top Layer w10: X5.5@5581.66,775 5581.66,944.6 5972.69,1335.63 5972.69,1358.39 5958.93,1372.15 H15.2@5958.93,1378.93 5935,1402.87 5935,2035.4 v1(6319.8,2420.2)
  Bottom Layer w10: H15.2@5958.93,1378.93 6044.44,1293.43 R111.2@6044.44,959.48 ; U21.26@6055.36,2328.58 6228.18,2328.58 v1(6319.8,2420.2)
G178: H15.3 R113.2 U21.27 X5.6 | length 2711.1
  Top Layer w10: X5.6@5601.34,775 5601.34,941.15 5994.29,1334.1 H15.3@5994.29,1414.29 ; H15.3@5994.96,1414.29 5994.96,2038.79 6005,2048.83 6005,2065.8 v1(6339.6,2400.4)
  Bottom Layer w10: H15.3@5994.29,1414.29 6074.44,1334.14 R113.2@6074.44,989.48 ; U21.27@6055.36,2308.9 6248.1,2308.9 v1(6339.6,2400.4)
G179: H15.4 R115.2 U21.28 X5.7 | length 2691.3
  Top Layer w10: X5.7@5620.12,798.52 5620.12,937.31 6029.65,1346.83 6029.65,2050.85 v1(6359.4,2380.6)
  Bottom Layer w10: H15.4@6029.65,1449.65 6104.44,1374.85 R115.2@6104.44,1019.48 ; U21.28@6055.36,2289.21 6268,2289.21 v1(6359.4,2380.6)
G180: H15.5 R117.2 U21.29 X5.8 | length 2698.7
  Top Layer w10: X5.8@5640,794.24 5640,934.56 6065,1359.56 H15.5@6065,1485 6065,2046.61 v1(6379.2,2360.8)
  Bottom Layer w10: U21.29@6055.36,2269.53 6287.92,2269.53 v1(6379.2,2360.8) ; H15.5@6065,1485 6134.44,1415.56 R117.2@6134.44,1049.48
G181: H15.6 R119.2 U21.30 X5.9 | length 2707.9
  Top Layer w10: X5.9@5660,787.99 5660,931.93 6100.36,1372.28 H15.6@6100.36,1520.36 6100.36,2042.37 v1(6398.99,2341.01)
  Bottom Layer w10: U21.30@6055.36,2249.84 6307.83,2249.84 v1(6398.99,2341.01) ; H15.6@6100.36,1520.36 6164.44,1456.27 R119.2@6164.44,1079.48
G182: H15.7 R121.2 U21.31 X5.10 | length 2695.9
  Top Layer w10: X5.10@5680,797.99 5680,929.3 6135.71,1385.01 H15.7@6135.71,1555.71 6135.71,2038.12 v1(6418.79,2321.21)
  Bottom Layer w10: U21.31@6055.36,2230.16 6327.75,2230.16 v1(6418.79,2321.21) ; H15.7@6135.71,1555.71 6194.44,1496.98 R121.2@6194.44,1114.48
G183: H15.8 R123.2 U21.32 X5.11 | length 2705.3
  Top Layer w10: X5.11@5700,793.67 5700,926.67 6170.4,1397.07 6170.4,2033.21 v1(6438.59,2301.41)
  Bottom Layer w10: U21.32@6055.36,2210.47 6347.66,2210.47 v1(6438.59,2301.41) ; H15.8@6171.07,1591.07 6229.44,1532.69 R123.2@6229.44,1144.48
G184: H15.9 R125.2 U21.33 X5.12 | length 2728.1
  Top Layer w10: X5.12@5719.45,775 5718.54,775.91 5718.54,812.67 5718.46,812.76 5718.46,922.51 6205.75,1409.8 6205.75,2028.97 v1(6458.39,2281.61)
  Bottom Layer w10: U21.33@6055.36,2190.79 6367.57,2190.79 v1(6458.39,2281.61) ; H15.9@6206.42,1626.42 6259.44,1573.4 R125.2@6259.44,1174.48
G185: H15.10 R127.2 U21.34 X5.13 | length 2728.7
  Top Layer w10: X5.13@5739.14,775 5738.23,775.91 5738.23,812.67 5738.15,812.76 5738.15,919.57 6241.11,1422.53 6241.11,1655.67 H15.10@6238.39,1658.39 ; H15.10@6241.78,1661.78 6241.78,2025.39 v1(6478.19,2261.81)
  Bottom Layer w10: U21.34@6055.36,2171.1 6387.48,2171.1 v1(6478.19,2261.81) ; H15.10@6241.78,1661.78 6289.44,1614.11 R127.2@6289.44,1204.48
G186: H15.11 R129.2 U21.35 X5.14 | length 2734.3
  Top Layer w10: X5.14@5758.82,775 5757.91,775.91 5757.91,812.67 5757.83,812.76 5757.83,916.62 6276.46,1435.25 6276.46,2020.48 v1(6497.99,2242.01)
  Bottom Layer w10: U21.35@6055.36,2151.42 6407.4,2151.42 v1(6497.99,2242.01) ; H15.11@6277.13,1697.13 6319.44,1654.82 R129.2@6319.44,1234.48
G187: H15.12 R131.2 U21.36 X5.15 | length 2739.5
  Top Layer w10: X5.15@5778.51,775 5777.6,775.91 5777.6,812.67 5777.52,812.76 5777.52,913.68 6312.49,1448.65 H15.12@6312.49,1732.49 6312.49,2016.91 v1(6517.79,2222.21)
  Bottom Layer w10: U21.36@6055.36,2131.73 6427.31,2131.73 v1(6517.79,2222.21) ; H15.12@6312.49,1732.49 6354.44,1690.53 R131.2@6354.44,1264.48
G188: H15.13 R133.2 U21.37 X5.16 | length 2922
  Top Layer w10: X5.16@5798.19,775 5797.28,775.91 5797.28,812.67 5797.2,812.76 5797.2,910.74 6350,1463.54 6350,1765.69 H15.13@6347.84,1767.84 6347.84,2007.84 v1(6540,2200)
  Bottom Layer w10: U21.37@5998.27,2074.64 5998.27,2034.21 6052.48,1980 6320,1980 v1(6540,2200) ; H15.13@6347.84,1767.84 6385.1,1730.59 6385.1,1318.23 6386.49,1316.84 R133.2@6386.49,1292.43
G189: H15.14 R135.2 U21.38 X5.17 | length 2958
  Top Layer w10: X5.17@5817.88,775 5816.97,775.91 5816.97,812.67 5816.89,812.76 5816.89,907.8 6383.2,1474.11 H15.14@6383.2,1803.2 6383.87,1803.87 6383.87,1998.87 v1(6565,2180)
  Bottom Layer w10: U21.38@5978.58,2074.64 5978.58,2031.27 6049.54,1960.31 6345.31,1960.31 v1(6565,2180) ; H15.14@6383.2,1803.2 6411.49,1774.91 R135.2@6411.49,1322.43
G190: H15.15 R137.2 U21.39 X5.18 | length 3002.9
  Top Layer w10: X5.18@5837.56,775 5837.47,775.09 5837.47,905.76 6418.49,1486.77 6418.49,1809.43 6418.19,1809.73 6418.19,1834.59 H15.15@6414.22,1838.55 ; H15.15@6418.55,1838.55 6418.55,1988.55 v1(6590,2160)
  Bottom Layer w10: U21.39@5958.9,2074.64 5958.9,2028.33 6046.6,1940.63 6370.63,1940.63 v1(6590,2160) ; H15.15@6418.55,1838.55 6418.55,1790.47 6444.44,1764.58 R137.2@6444.44,1349.48
G191: H15.16 R140.2 U21.40 X5.19 | length 3043.8
  Top Layer w10: X5.19@5857.25,775 5857.16,775.09 5857.16,902.82 6434.49,1480.14 6434.49,1541.42 6453.91,1560.84 H15.16@6453.91,1873.91 6453.91,1968.91 v1(6620,2135)
  Bottom Layer w10: U21.40@5939.21,2074.64 5939.21,2025.39 6043.66,1920.94 6405.94,1920.94 v1(6620,2135) ; H15.16@6453.91,1873.91 6476.49,1851.33 R140.2@6476.49,1377.43
G192: H13.1 R142.2 U8.12 X5.20 | length 2706.4
  Top Layer w10: X5.20@5876.93,775 5876.02,775.91 5876.02,812.67 5875.94,812.76 5875.94,898.97 6450.49,1473.51 6450.49,1534.79 6613.22,1697.53 H13.1@6613.22,1841.78
  Bottom Layer w10: R142.2@6580.21,1335.24 6580.21,1760.68 6613.22,1793.69 H13.1@6613.22,1841.78 ; H13.1@6615,1836.53 6615,1860.77 6613.22,1862.54 6615,1864.32 6615,2049.58 6963.69,2398.27 U8.12@7069.64,2398.27
G193: H13.2 R144.2 U8.11 X5.21 | length 2668.4
  Top Layer w10: X5.21@5896.62,775 5895.71,775.91 5895.71,812.67 5895.63,812.76 5895.63,896.03 6466.49,1466.89 6466.49,1528.16 6648.58,1710.25 H13.2@6648.58,1806.42
  Bottom Layer w10: R144.2@6612.26,1302.29 6612.26,1770.1 H13.2@6648.58,1806.42 ; H13.2@6654.2,1806.42 6654.2,1826.16 6655,1826.96 6655,1834.5 6656.06,1835.56 6656.06,1847.99 6655,1849.05 6655,2066.95 6966.63,2378.58 U8.11@7069.64,2378.58
G194: H13.3 R146.2 U8.10 X5.22 | length 2632.7
  Top Layer w10: X5.22@5916.3,775 5915.39,775.91 5915.39,812.67 5915.31,812.76 5915.31,893.08 6482.49,1460.26 6482.49,1521.53 6683.93,1722.98 H13.3@6683.93,1771.07
  Bottom Layer w10: R146.2@6647.26,1272.29 6647.26,1734.39 H13.3@6683.93,1771.07 ; H13.3@6689.55,1771.07 6689.55,1791.16 6690,1791.61 6690,2079.32 6969.58,2358.9 U8.10@7069.64,2358.9
G195: H13.4 R148.2 U8.9 X5.23 | length 2609.6
  Top Layer w10: X5.23@5935.99,775 5935.08,775.91 5935.08,812.67 5935,812.76 5935,890.14 6498.49,1453.63 6498.49,1514.91 H13.4@6719.29,1735.71
  Bottom Layer w10: R148.2@6677.26,1242.29 6677.26,1693.68 H13.4@6719.29,1735.71 ; H13.4@6720,1728.11 6720,2086.7 6972.51,2339.21 U8.9@7069.64,2339.21
G196: H13.5 R150.2 U8.8 X5.24 | length 2559.8
  Top Layer w10: X5.24@5955.67,775 5954.76,775.91 5954.76,812.67 5954.68,812.76 5954.68,887.2 6514.49,1447 6514.49,1460.2 H13.5@6754.64,1700.36
  Bottom Layer w10: R150.2@6710.21,1210.24 6710.21,1655.92 H13.5@6754.64,1700.36 ; H13.5@6755,1710.89 6755,2099.07 6975.46,2319.53 U8.8@7069.64,2319.53
G197: H13.6 R152.2 U8.7 X5.25 | length 2555.9
  Top Layer w10: X5.25@5975.36,775 5974.45,775.91 5974.45,812.67 5974.37,812.76 5974.37,884.26 6735.75,1645.64 6762.7,1645.64 6782.05,1665 H13.6@6790,1665
  Bottom Layer w10: R152.2@6740.21,1180.24 6740.21,1615.21 H13.6@6790,1665 ; H13.6@6795,1665.18 6795,2116.44 6978.4,2299.84 U8.7@7069.64,2299.84
G198: H13.7 R154.2 U8.6 X5.26 | length 2553.7
  Top Layer w10: X5.26@5995.04,775 5994.13,775.91 5994.13,812.67 5994.05,812.76 5994.05,881.31 6742.38,1629.64 H13.7@6825.36,1629.64
  Bottom Layer w10: R154.2@6770.21,1150.24 6770.21,1574.5 H13.7@6825.36,1629.64 6825.36,2124.17 6981.35,2280.16 U8.6@7069.64,2280.16
G199: H13.8 R156.2 U8.5 X5.27 | length 2548.8
  Top Layer w10: X5.27@6014.73,775 6014.64,775.09 6014.64,879.28 6729.65,1594.29 H13.8@6860.71,1594.29
  Bottom Layer w10: R156.2@6802.26,1117.29 6802.26,1535.84 H13.8@6860.71,1594.29 ; H13.8@6865,1594.23 6865,2141.19 6984.28,2260.47 U8.5@7069.64,2260.47
G200: H13.9 R158.2 U8.4 X5.28 | length 2547.5
  Top Layer w10: X5.28@6034.41,775 6033.5,775.91 6033.5,812.67 6033.42,812.76 6034.32,813.66 6034.32,876.33 6716.93,1558.93 H13.9@6896.07,1558.93
  Bottom Layer w10: R158.2@6835.21,1085.24 6835.21,1498.08 H13.9@6896.07,1558.93 6896.07,1566.88 6905,1575.82 6905,2158.56 6987.23,2240.79 U8.4@7069.64,2240.79
G201: H13.10 R160.2 U8.3 X5.29 | length 2531.4
  Top Layer w10: X5.29@6054.1,775 6054.01,775.09 6054.01,873.4 6704.2,1523.58 H13.10@6931.42,1523.58
  Bottom Layer w10: R160.2@6867.86,1052.86 6867.86,1460.01 H13.10@6931.42,1523.58 ; H13.10@6935,1534.28 6935,2165.93 6990.17,2221.1 U8.3@7069.64,2221.1
G202: H13.11 R162.2 U8.2 X5.30 | length 2535.2
  Top Layer w10: X5.30@6073.78,775 6072.87,775.91 6072.87,812.67 6072.79,812.76 6072.79,869.54 6691.47,1488.22 H13.11@6966.78,1488.22
  Bottom Layer w10: R162.2@6900.81,1020.81 6900.81,1422.25 H13.11@6966.78,1488.22 ; H13.11@6970,1492.22 6970,2178.3 6993.12,2201.42 U8.2@7069.64,2201.42
G203: H13.12 R164.2 U8.1 X5.31 | length 2526.9
  Top Layer w10: X5.31@6093.47,775 6092.56,775.91 6092.56,812.67 6092.48,812.76 6092.48,866.6 6678.74,1452.87 H13.12@7002.13,1452.87
  Bottom Layer w10: R164.2@6935.81,990.81 6935.81,1386.54 H13.12@7002.13,1452.87 7002.13,2175.68 7007.99,2181.53 7069.45,2181.53 U8.1@7069.64,2181.73
G204: H13.13 R166.2 U8.48 X5.32 | length 2471.4
  Top Layer w10: X5.32@6113.15,775 6112.24,775.91 6112.24,812.67 6112.16,812.76 6112.16,863.66 6666.01,1417.51 H13.13@7037.49,1417.51
  Bottom Layer w10: R166.2@6967.86,962.86 6967.86,1347.88 H13.13@7037.49,1417.51 7126.73,1506.76 U8.48@7126.73,2124.64
G205: H13.14 R168.2 U8.47 X5.33 | length 2498.5
  Top Layer w10: X5.33@6132.84,775 6131.93,775.91 6131.93,812.67 6131.85,812.76 6131.85,860.72 6653.29,1382.16 H13.14@7072.84,1382.16
  Bottom Layer w10: R168.2@6999.91,929.91 6999.91,1309.22 H13.14@7072.84,1382.16 7146.42,1455.73 U8.47@7146.42,2124.64
G206: H13.15 R170.2 U8.46 X5.34 | length 2522.3
  Top Layer w10: X5.34@6152.52,775 6151.61,775.91 6151.61,812.67 6151.53,812.76 6151.53,857.77 6640.56,1346.8 H13.15@7108.2,1346.8
  Bottom Layer w10: R170.2@7030.81,900.81 7030.81,1269.41 H13.15@7108.2,1346.8 7166.1,1404.71 U8.46@7166.1,2124.64
G207: H13.16 R172.2 U8.45 X5.35 | length 2551.5
  Top Layer w10: X5.35@6172.21,775 6171.3,775.91 6171.3,812.67 6171.22,812.76 6171.22,854.84 6627.83,1311.45 H13.16@7143.55,1311.45
  Bottom Layer w10: R172.2@7057.86,867.86 7057.86,1225.75 H13.16@7143.55,1311.45 7185.79,1353.68 U8.45@7185.79,2124.64
G208: H16.1 R174.2 U8.25 X5.36 | length 4680.8
  Top Layer w10: X5.36@6191.89,775 6191.89,852.88 6579.01,1240 7185,1240 7320,1375 7320,2520 6877.69,2962.32 6823.63,2962.32 6755.63,3030.32 6754.69,3030.32 H16.1@6740,3045
  Bottom Layer w10: R174.2@6759.84,3296.87 6759.84,3064.84 H16.1@6740,3045 6755.31,3045 6755.31,3030.63 6935.63,2850.32 7019.69,2850.32 7457.59,2412.41 7457.59,2404.13 7451.73,2398.27 U8.25@7400.36,2398.27
G209: H16.2 R176.2 U8.26 X5.37 | length 4723.2
  Top Layer w10: X5.37@6211.58,775 6211.58,849.94 6551.64,1190 7185,1190 7350,1355 7350,2525 6896.69,2978.32 6857.63,2978.32 6790.95,3045 H16.2@6790,3045
  Bottom Layer w10: R176.2@6805.53,3296.87 6805.53,3060.53 H16.2@6790,3045 6805.31,3045 6805.31,3030.63 6969.63,2866.32 7053.12,2866.32 7492.22,2427.22 7492.22,2395.8 7475,2378.58 U8.26@7400.36,2378.58
G210: H16.3 R178.2 U8.27 X5.38 | length 4764.6
  Top Layer w10: X5.38@6231.26,775 6231.17,775.09 6231.17,846.91 6524.26,1140 7185,1140 7366,1321 7366,2554 6925.69,2994.32 6891.63,2994.32 6840.95,3045 H16.3@6840,3045
  Bottom Layer w10: R178.2@6851.22,3296.87 6851.22,3056.22 H16.3@6840,3045 6855.31,3045 6855.31,3030.63 7003.63,2882.32 7077.69,2882.32 7537.5,2422.5 7537.5,2396.4 7500,2358.9 U8.27@7400.36,2358.9
G211: H16.4 R180.2 U8.28 X5.39 | length 4791.6
  Top Layer w10: X5.39@6250.95,775 6250.86,775.09 6250.86,843.97 6496.89,1090 7185,1090 7382,1287 7382,2573 6944.69,3010.32 6925.63,3010.32 6890.95,3045 H16.4@6890,3045
  Bottom Layer w10: R180.2@6896.91,3296.87 6896.91,3051.91 H16.4@6890,3045 6905.31,3045 6905.31,3030.63 7037.63,2898.32 7096.69,2898.32 7570,2425 7570,2375 7534.21,2339.21 U8.28@7400.36,2339.21
G212: H16.5 R182.2 U8.29 X5.40 | length 4849
  Top Layer w10: X5.40@6270.63,775 6270.54,775.09 6270.54,841.02 6469.52,1040 7185,1040 7430,1285 7430,2555 H16.5@6940,3045
  Bottom Layer w10: R182.2@6942.6,3296.87 6942.6,3047.6 H16.5@6940,3045 6955.31,3045 6955.31,3030.63 7071.63,2914.32 7120.69,2914.32 7610,2425 7610,2365 7564.53,2319.53 U8.29@7400.36,2319.53
G213: H16.6 R184.2 U8.30 X5.41 | length 4905.8
  Top Layer w10: X5.41@6290.32,775 6290.32,838.17 6442.15,990 7185,990 7480,1285 7480,2555 H16.6@6990,3045
  Bottom Layer w10: R184.2@6988.3,3296.87 6988.3,3280.73 6990,3279.03 H16.6@6990,3045 7005.31,3045 7005.31,3030.63 7105.63,2930.32 7154.69,2930.32 7635,2450 7635,2355 7579.84,2299.84 U8.30@7400.36,2299.84
G214: H16.7 R186.2 U8.31 X5.42 | length 4961.6
  Top Layer w10: X5.42@6310,775 6310,835 6415,940 7185,940 7530,1285 7530,2555 H16.7@7040,3045
  Bottom Layer w10: R186.2@7033.99,3296.87 7033.99,3280.73 7040,3274.72 H16.7@7040,3045 7055.31,3045 7055.31,3030.63 7139.63,2946.32 7178.69,2946.32 7665,2460 7665,2352.51 7592.65,2280.16 U8.31@7400.36,2280.16
G215: H16.8 R188.2 U8.32 X5.43 | length 5004.6
  Top Layer w10: X5.43@6329.69,775 6329.69,832.06 6387.63,890 7185,890 7580,1285 7580,2555 H16.8@7090,3045
  Bottom Layer w10: R188.2@7079.68,3296.87 7079.68,3280.73 7090,3270.41 H16.8@7090,3045 7105.31,3045 7105.31,3030.63 7173.63,2962.32 7197.69,2962.32 7690,2470 7690,2354.88 7595.59,2260.47 U8.32@7400.36,2260.47
G216: H16.9 R190.2 U8.33 X5.44 | length 5044.8
  Top Layer w10: X5.44@6349.37,775 6350.28,775.91 6350.28,803.27 6387.01,840 7185,840 7630,1285 7630,2555 H16.9@7140,3045
  Bottom Layer w10: R190.2@7125.37,3296.87 7125.37,3059.63 H16.9@7140,3045 7155.31,3045 7155.31,3030.63 7207.63,2978.32 7231.69,2978.32 7720,2490 7720,2362.25 7598.54,2240.79 U8.33@7400.36,2240.79
G217: H16.10 R192.2 U8.34 X5.45 | length 5076.5
  Top Layer w10: X5.45@6369.06,775 6369.06,789.09 6369.97,790 7185,790 7680,1285 7680,2555 H16.10@7190,3045
  Bottom Layer w10: R192.2@7171.06,3296.87 7171.06,3063.94 H16.10@7190,3045 7205.31,3045 7205.31,3030.63 7745,2490.95 7745,2364.62 7601.48,2221.1 U8.34@7400.36,2221.1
